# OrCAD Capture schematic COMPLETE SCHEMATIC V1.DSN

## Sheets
1 PAGE1: size A
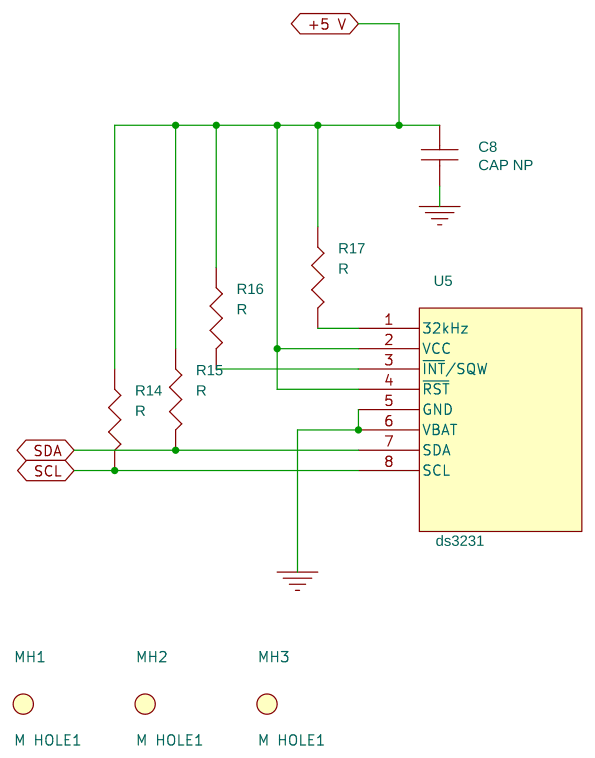
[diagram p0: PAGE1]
2 SizeB: size B; title: Item Tracking System; rev: C; note: Team1 SR GS AT MM
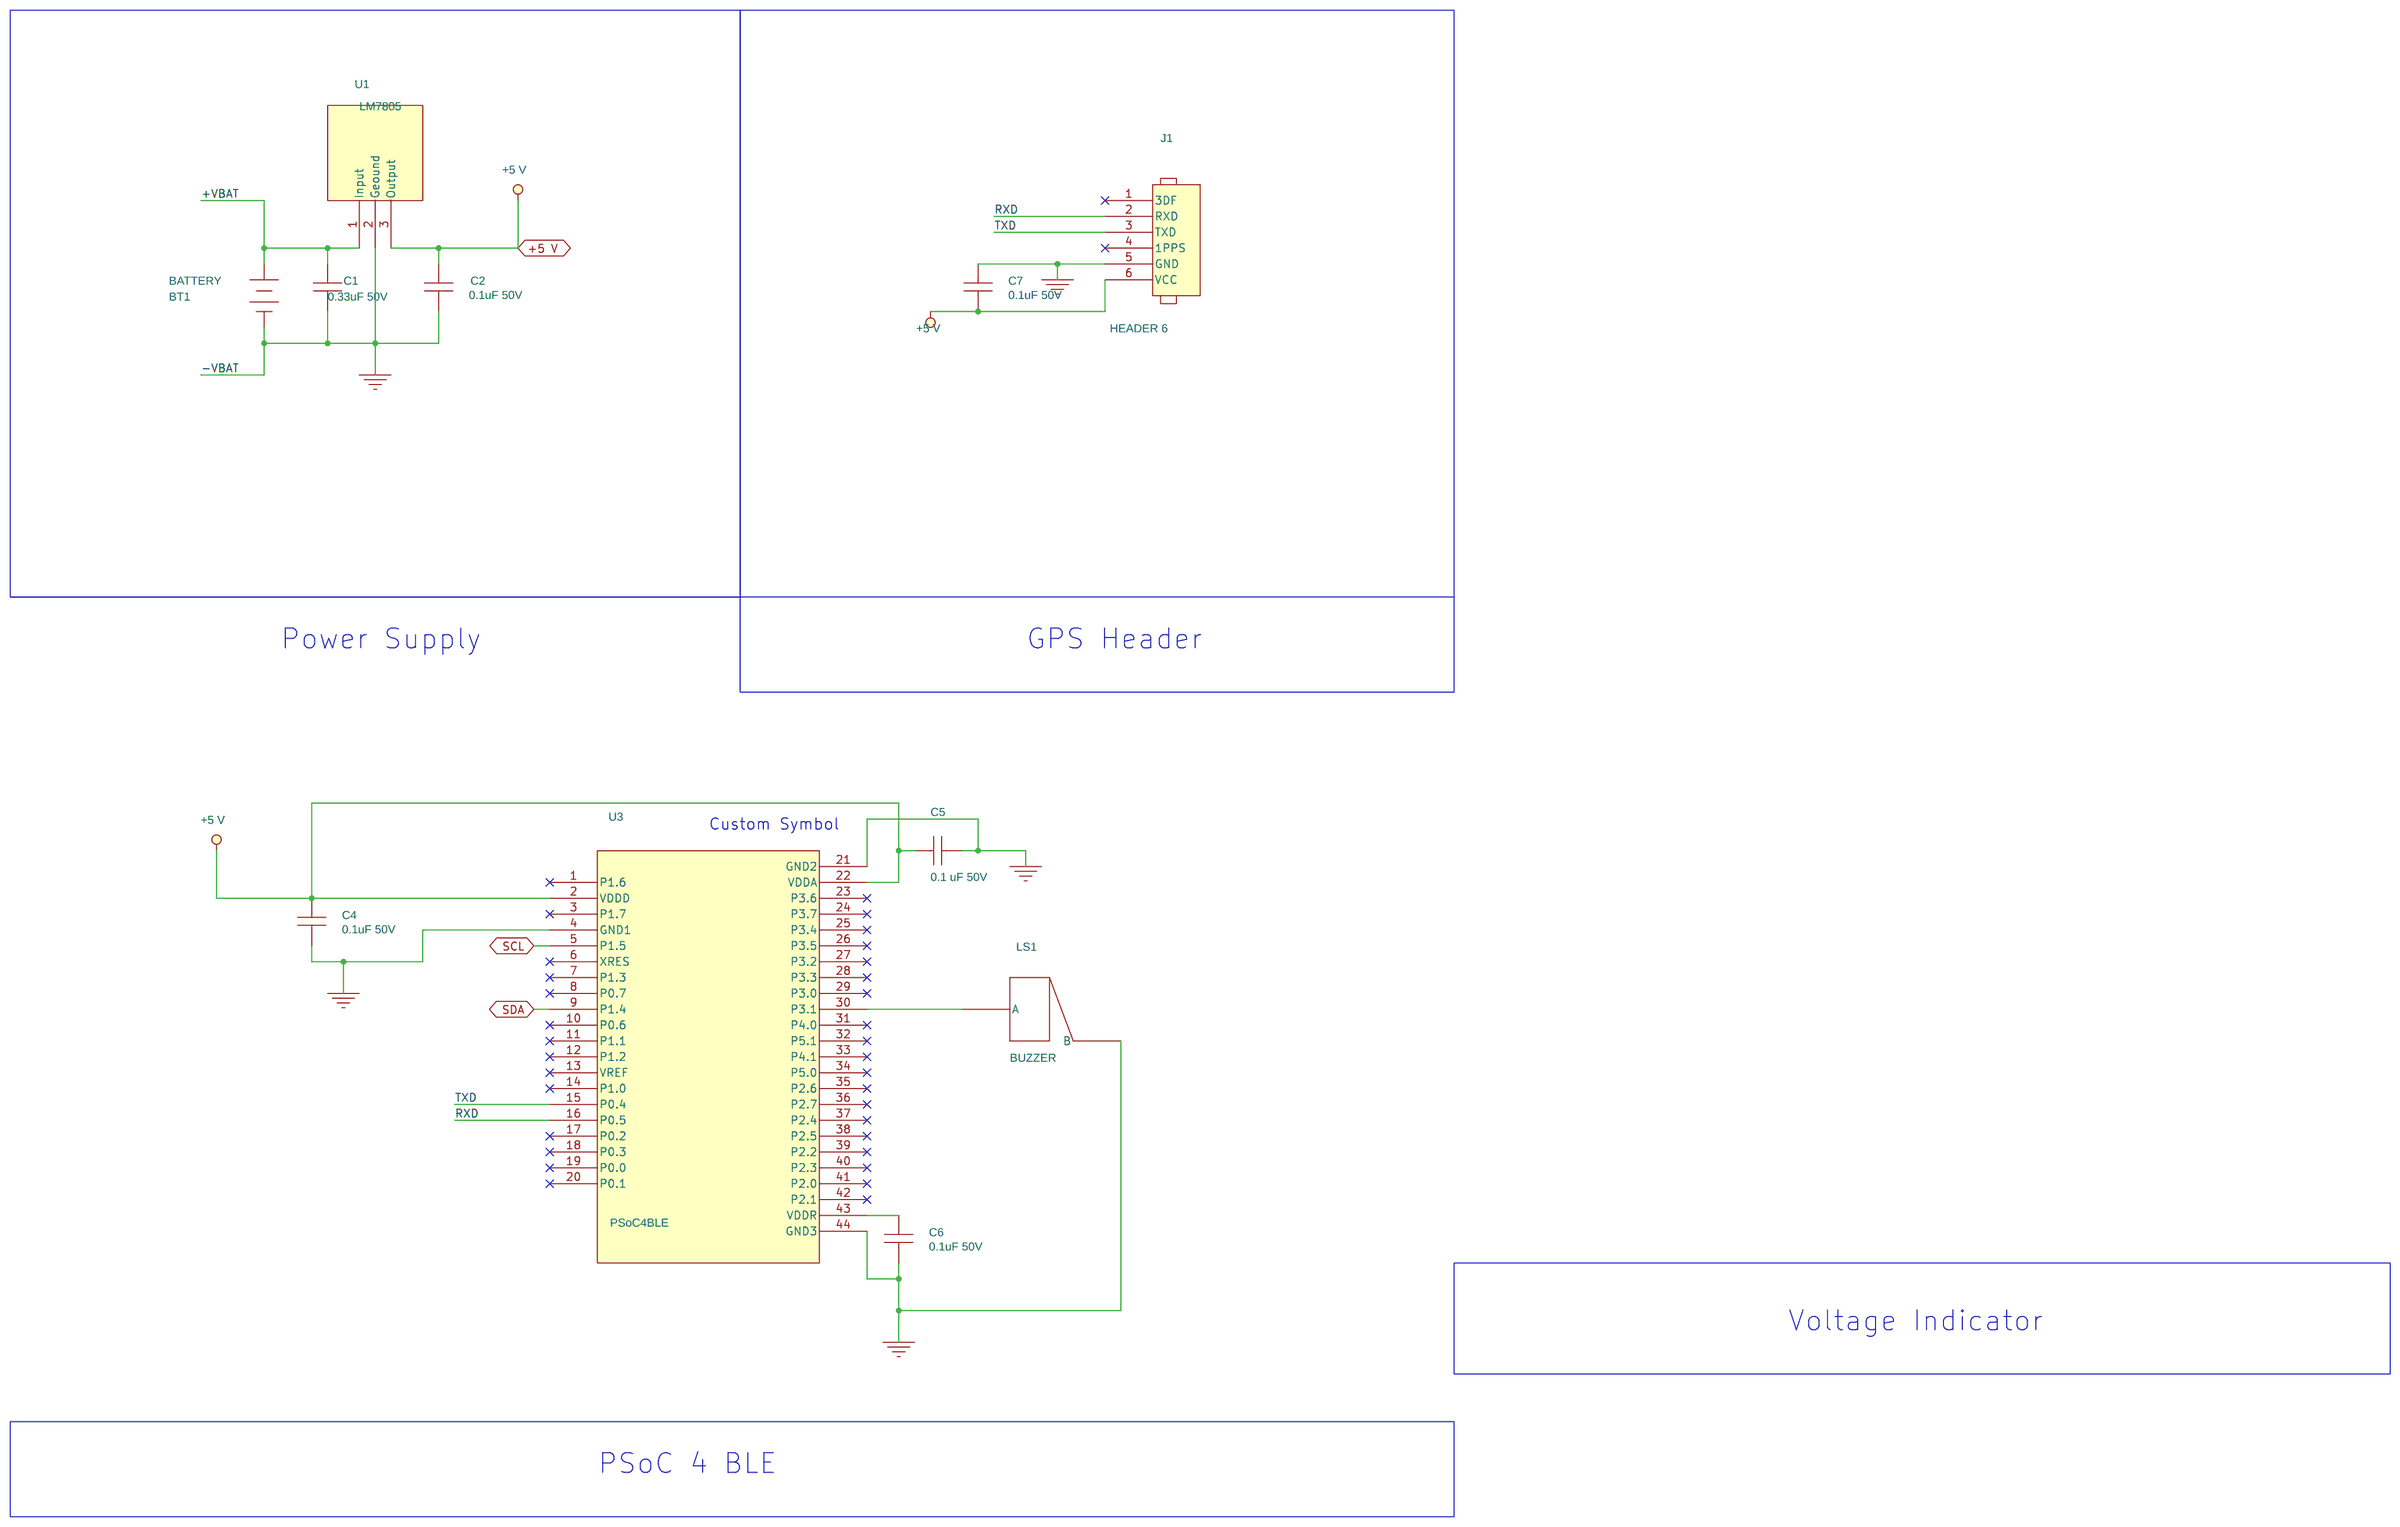
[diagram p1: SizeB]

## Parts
sheet PAGE1
C8  CAP NP  [Cap1]
MH1  M HOLE1  [mounting]
MH2  M HOLE1  [mounting]
MH3  M HOLE1  [mounting]
R14  R  [AXRC07]
R15  R  [AXRC07]
R16  R  [AXRC07]
R17  R  [AXRC07]
U5  ds3231  [SOIC8]
sheet SizeB
BT1  BATTERY  [2pos5mmCON]
C1  0.33uF 50V  [Cap1]
C2  0.1uF 50V  [Cap1]
C4  0.1uF 50V  [Cap1]
C5  0.1 uF 50V  [Cap1]
C6  0.1uF 50V  [Cap1]
C7  0.1uF 50V  [Cap1]
J1  HEADER 6  [sip6]
LS1  BUZZER  [buzzer]
U1  LM7805  [TO220AB]
U3  PSoC4BLE  [PSOC4BLE]

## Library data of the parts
C1 C2 C4-C8 = CAP_NP
MH1-MH3 = M_HOLE1
R14-R17 = R
U5 = ds3231_0
BT1 = BATTERY
J1 = HEADER_6_0
LS1 = BUZZER
U1 = Linear_regulator
U3 = PSoC4BLE_0

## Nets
+VBAT: BT1.1(+) C1.1 U1.1(Input)
GND: BT1.2(-) C1.2 C2.2 C4.2 C5.2 C6.2 C7.1 C8.2 J1.5(GND) LS1.2(B) U1.2(Geound) U3.4(GND1) U3.21(GND2) U3.44(GND3) U5.5(GND) U5.6(VBAT)
+5 V: C2.1 C4.1 C5.1 C7.2 C8.1 J1.6(VCC) R14.1 R15.1 R16.1 R17.1 U1.3(Output) U3.2(VDDD) U3.22(VDDA) U5.2(VCC) U5.4(~{RST})
RXD: J1.2(RXD) U3.16(P0.5)
SCL: R14.2 U3.5(P1.5) U5.8(SCL)
SDA: R15.2 U3.9(P1.4) U5.7(SDA)
TXD: J1.3(TXD) U3.15(P0.4)
N57082: C6.1 U3.43(VDDR)
N86841: R16.2 U5.3(~{INT}/SQW)
N86845: R17.2 U5.1(32kHz)
N89522: LS1.1(A) U3.30(P3.1)

Not connected (* = marked no-connect by the designer): J1 1(3DF)* 4(1PPS)*; U3 1(P1.6)* 3(P1.7)* 6(XRES)* 7(P1.3)* 8(P0.7)* 10(P0.6)* 11(P1.1)* 12(P1.2)* 13(VREF)* 14(P1.0)* 17(P0.2)* 18(P0.3)* 19(P0.0)* 20(P0.1)* 23(P3.6)* 24(P3.7)* 25(P3.4)* 26(P3.5)* 27(P3.2)* 28(P3.3)* 29(P3.0)* 31(P4.0)* 32(P5.1)* 33(P4.1)* 34(P5.0)* 35(P2.6)* 36(P2.7)* 37(P2.4)* 38(P2.5)* 39(P2.2)* 40(P2.3)* 41(P2.0)* 42(P2.1)*

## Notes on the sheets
sheet 2
- Power Supply
- GPS Header
- Custom Symbol
- Voltage Indicator
- PSoC 4 BLE
